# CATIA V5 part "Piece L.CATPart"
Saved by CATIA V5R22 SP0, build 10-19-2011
Part number: Piece L
Bounding box of the stored display mesh (mm): x -8.945 to 57.055, y 0 to 50, z 0 to 50
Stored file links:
  D:\CAO_PER_MODIF_2025\CAO_PER_pick&place_2024P\Sous_Ensemble_Flacon\Piece L.CATPart
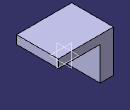
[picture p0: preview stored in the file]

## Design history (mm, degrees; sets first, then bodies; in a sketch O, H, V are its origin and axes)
Body1 (main body)
  Sketch1 on zx-plane, origin (7.0546, 0, 0), H (-1, 0, 0), V (0, 0, 1)
    line L1 (0, 0) -> (16, 0)
    line L2 (16, 0) -> (16, 50)
    line L3 (16, 50) -> (-50, 50)
    line L4 (-50, 50) -> (-50, 40)
    line L5 (-50, 40) -> (0, 40)
    point P5 (0, 40)
    line L6 (0, 40) -> (0, 0)
    length L1 = 16
    distance L1 L5 = 40
    length L4 = 10
    distance L6 L4 = 50
    horizontal: L1 H, L3 H, L5 H
    vertical: L2 V, L4 V, L6 V
    coincidence: P5 V
  Pad1: profile Sketch1, direction (0, 1, 0), length 50
  Sketch2 on face of Pad1 from Sketch1.L6, origin (7.0546, 29.3013, 23.441), H (0, 1, 0), V (0, 0, 1)
    point P1 (-4.3013, -3.441)
    reference projected line E1 (-29.3013, -23.441) -> (20.6987, -23.441) from edge [face of Pad1 from Sketch1.L1 | face of Pad1 from Sketch1.L6]
    reference projected line E2 (-29.3013, 16.559) -> (-29.3013, -23.441) from edge [start face of Pad1 | face of Pad1 from Sketch1.L6]
    distance P1 E1 = 20
    distance P1 E2 = 25
  Hole1: placed by Sketch2, at (7.0546, 25, 20) direction (-1, 0, 0), diameter 6.647, through (limit type 3), threaded "M8", thread diameter 8, thread depth 10, pitch 1.25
